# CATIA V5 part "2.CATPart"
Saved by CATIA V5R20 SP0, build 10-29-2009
Part number: 2
Bounding box of the stored display mesh (mm): x -60 to 60, y -60 to 60, z -70 to 90
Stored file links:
  E:\Ehsan\Amoozesh\CATIA\CATIA Course\Advanced\Videos\Session-19\2.CATPart
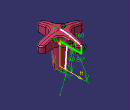
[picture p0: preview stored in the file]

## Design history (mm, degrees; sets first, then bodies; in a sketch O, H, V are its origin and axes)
AxisSystem1: origin (0, 0, 0), X (1, 0, 0), Y (0, 1, 0), Z (0, 0, 1)
Set1 "Sketches"
  Sketch1 on XY plane of AxisSystem1, origin (0, 0, 0), H (1, 0, 0), V (0, 1, 0)
    arc A1 centre (30, 30) radius 20 from (10, 30) to (30, 10) ccw
    point P1 (30, 30)
    line L1 (10, 70) -> (10, 30)
    line L2 (30, 10) -> (70, 10)
    distance P1 V = 30
    distance P1 H = 30
    radius A1 = 20
    length L2 = 40
    length L1 = 40
    vertical: L1 V
    horizontal: L2 H
    tangency: L2 A1, L1 A1
  Sketch2 on YZ plane of AxisSystem1, origin (0, 0, 0), H (0, 1, 0), V (0, 0, 1)
    point P1 (15, 0)
    line L1 (15, 0) -> (19.1956, 60)
    point P2 (19.1956, 60)
    line L2 (0, 60) -> (60, 60)
    point P3 (60, 60)
    line L3 (60, 60) -> (60, 78.324)
    arc A1 centre (0, -70) radius 160 from (60, 78.324) to (0, 90) ccw
    point P6 (0, 90)
    distance P2 H = 60
    angle L1 H = 86
    distance P3 V = 60
    radius A1 = 160
    distance P6 O = 90
    distance O P1 = 15
    horizontal: L2 H
    vertical: L3 V
    coincidence: P6 V, P2 L2
Set2 "Surfaces"
  Extrude1: Element1 sketch element, Lim1 80, Lim2 0, Direction edge [XY plane of AxisSystem1 | ZX plane of AxisSystem1]
  Revol1: Element1 sketch element, Line edge [ZX plane of AxisSystem1 | YZ plane of AxisSystem1], Angle1 0
  Revol2: Element1 sketch element, Line edge [ZX plane of AxisSystem1 | YZ plane of AxisSystem1], Angle1 0
  Revol3: Element1 sketch element, Line edge [ZX plane of AxisSystem1 | YZ plane of AxisSystem1], Angle1 0
  Trim1: Trimmed (Revol3; Extrude1; Revol2)
  Join1: Elements (Revol1; Trim1)
  Symmetry1: ToTransfor Fillet1, Reference ZX plane of AxisSystem1
  Fillet1: radius 3, on edge [face of Revol1 | face of Extrude2 from Sketch1.A1]; edge [face of Extrude1 | face of Extrude2 from Sketch1.A1]
  Extrude2: Element1 Sketch1, Lim1 100, Lim2 0
  Fillet2: radius 10, on edge [face of Extrude2 from Sketch1.L2 | face of Revol2]; edge [face of Revol2 | face of Extrude2 from Sketch1.L1]
  Trim2: Trimmed (Join1; Extrude2)
  Join2: Elements (Symmetry1; Fillet1)
  Symmetry2: ToTransfor Join2, Reference YZ plane of AxisSystem1
  Join3: Elements (Symmetry2; Join2)
Body1 (main body)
